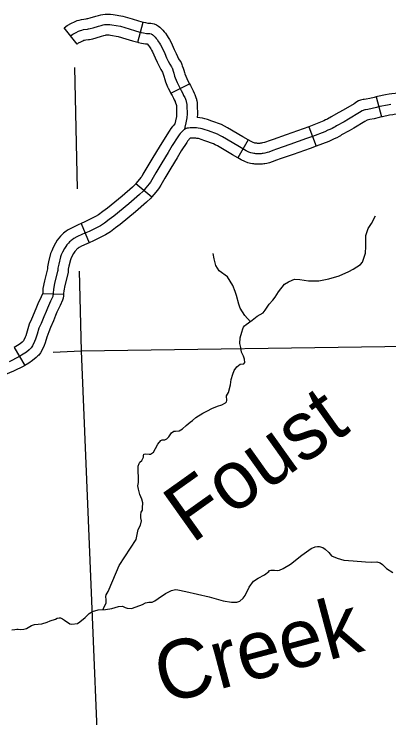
# Model space of a CAD drawing. Extents: x 1720274 to 1751788, y 372074 to 391887.
# Drawn here: x 1730745 to 1731172, y 380014 to 380815 of the extents above; entities that cross this region are included whole.
import ezdxf

# ---------------------------------------------------------------- set-up
doc = ezdxf.new("R2010")
doc.units = 0
for name, color, linetype in [('Level 32', 7, 'Continuous'), ('Level 35', 7, 'Continuous'), ('Level 4', 7, 'Continuous'), ('Level 5', 7, 'Continuous')]:
    doc.layers.add(name, color=color, linetype=linetype)

msp = doc.modelspace()

# ---------------------------------------------------------------- linework, layer by layer
at = {"layer": 'Level 32'}
for p, q in [((1730816.83, 380780.75), (1730801.96, 380799.21)), ((1730886.02, 380782.82), (1730892.18, 380805.71)), ((1730923.5, 380724.96), (1730944.67, 380735.61)), ((1731157.39, 380720.74), (1731163.41, 380697.82)), ((1731080.69, 380686.79), (1731088.89, 380664.55)), ((1731011.72, 380671.78), (1730999.96, 380651.21)), ((1730883.83, 380622.2), (1730902, 380606.98)), ((1730821.3, 380576.56), (1730830.71, 380554.8)), ((1730777.77, 380497.15), (1730801.45, 380496.39)), ((1730745.08, 380435.42), (1730757.36, 380415.15))]:
    msp.add_line(p, q, dxfattribs=at)
for points in [[(1730801.96, 380799.21), (1730805.47, 380802.03), (1730810.31, 380804.58), (1730813.73, 380806.22), (1730816.85, 380807.5), (1730819.18, 380808.15), (1730821.81, 380808.86), (1730827.28, 380809.66), (1730828.18, 380809.73), (1730829.15, 380809.9), (1730831.85, 380810.68), (1730838.09, 380812.56), (1730841.25, 380813.42), (1730843.85, 380814.13), (1730846.23, 380814.59), (1730848.96, 380814.91), (1730852.47, 380814.91), (1730854.94, 380814.86), (1730857.92, 380814.55), (1730868.99, 380812.69), (1730879.53, 380809.41), (1730886.58, 380807.22), (1730892.18, 380805.71)], [(1730809.4, 380789.98), (1730812.01, 380792.08), (1730815.63, 380793.99), (1730818.55, 380795.39), (1730820.72, 380796.28), (1730822.31, 380796.72), (1730824.21, 380797.23), (1730828.54, 380797.87), (1730829.65, 380797.95), (1730831.87, 380798.35), (1730835.21, 380799.32), (1730841.35, 380801.17), (1730844.35, 380801.99), (1730846.54, 380802.58), (1730848.06, 380802.88), (1730849.65, 380803.06), (1730852.35, 380803.06), (1730854.2, 380803.02), (1730856.31, 380802.8), (1730866.24, 380801.13), (1730876.01, 380798.1), (1730883.27, 380795.83), (1730889.6, 380794.13), (1730892.53, 380793.5), (1730896.01, 380792.91), (1730899.68, 380792.68), (1730901.08, 380792.46), (1730901.56, 380792.24), (1730902.6, 380791.54), (1730903.23, 380791.09), (1730903.75, 380790.57), (1730905.56, 380788.68), (1730906.82, 380787.24), (1730907.82, 380785.94), (1730909.71, 380783.34), (1730910.6, 380781.97), (1730911.9, 380779.97), (1730913.38, 380777.27), (1730916.67, 380769.89), (1730918.78, 380765.11), (1730920.41, 380761.51), (1730922.25, 380758.1), (1730924.4, 380754.81), (1730924.78, 380754.21), (1730925.01, 380753.68), (1730925.28, 380752.78), (1730926.08, 380750.02), (1730926.82, 380747.66), (1730927.75, 380744.39), (1730928.6, 380742.42), (1730930.87, 380736.88), (1730931.41, 380735.61), (1730934.15, 380730.15), (1730935.38, 380727.88), (1730937.25, 380724.49), (1730938.16, 380722.46), (1730939.36, 380720.14), (1730939.76, 380719.09), (1730940.52, 380717.03), (1730940.85, 380716.15), (1730941.2, 380714.97), (1730941.38, 380714.3), (1730941.54, 380713.63), (1730941.7, 380712.75), (1730941.75, 380712.08), (1730941.82, 380710.57), (1730941.99, 380701.42), (1730941.71, 380696.79), (1730940.5, 380691.11), (1730939.65, 380686.11), (1730939.16, 380683.65)], [(1730892.18, 380805.71), (1730892.39, 380805.65), (1730894.77, 380805.14), (1730897.37, 380804.7), (1730900.96, 380804.48), (1730904.56, 380803.91), (1730907.42, 380802.59), (1730909.35, 380801.28), (1730910.9, 380800.18), (1730912.22, 380798.86), (1730914.31, 380796.68), (1730915.99, 380794.75), (1730917.31, 380793.04), (1730919.48, 380790.06), (1730920.54, 380788.42), (1730922.08, 380786.05), (1730924, 380782.54), (1730927.5, 380774.7), (1730929.6, 380769.95), (1730931.04, 380766.77), (1730932.45, 380764.15), (1730934.34, 380761.26), (1730935.27, 380759.82), (1730936.18, 380757.72), (1730936.65, 380756.12), (1730937.43, 380753.46), (1730938.18, 380751.06), (1730938.94, 380748.36), (1730939.53, 380747), (1730941.79, 380741.46), (1730942.16, 380740.62), (1730944.67, 380735.61)], [(1730816.83, 380780.75), (1730818.54, 380782.13), (1730820.95, 380783.4), (1730823.37, 380784.56), (1730824.59, 380785.06), (1730825.43, 380785.29), (1730826.61, 380785.61), (1730829.8, 380786.08), (1730831.12, 380786.17), (1730834.6, 380786.81), (1730838.56, 380787.95), (1730844.62, 380789.78), (1730847.46, 380790.55), (1730849.23, 380791.03), (1730849.88, 380791.16), (1730850.34, 380791.21), (1730852.23, 380791.21), (1730853.46, 380791.19), (1730854.71, 380791.06), (1730863.48, 380789.58), (1730872.49, 380786.78), (1730879.97, 380784.45), (1730886.02, 380782.82)], [(1730886.02, 380782.82), (1730886.81, 380782.61), (1730890.29, 380781.86), (1730894.65, 380781.12), (1730896.51, 380781), (1730896.82, 380780.68), (1730897.65, 380779.72), (1730898.34, 380778.83), (1730899.94, 380776.63), (1730900.65, 380775.53), (1730901.71, 380773.9), (1730902.75, 380772), (1730905.84, 380765.08), (1730907.97, 380760.27), (1730909.79, 380756.25), (1730912.05, 380752.04), (1730914.03, 380749), (1730914.74, 380746.59), (1730915.47, 380744.27), (1730916.56, 380740.42), (1730917.67, 380737.84), (1730919.94, 380732.29), (1730920.67, 380730.6), (1730923.5, 380724.96)], [(1730944.66, 380735.64), (1730945.79, 380733.56), (1730947.86, 380729.79), (1730948.84, 380727.62), (1730950.19, 380724.99), (1730950.86, 380723.25), (1730951.62, 380721.17), (1730952.08, 380719.95), (1730952.61, 380718.17), (1730952.88, 380717.17), (1730953.14, 380716.04), (1730953.46, 380714.27), (1730953.58, 380712.82), (1730953.66, 380710.95), (1730953.84, 380701.17), (1730953.61, 380697.26)], [(1730923.5, 380724.96), (1730923.65, 380724.66), (1730924.98, 380722.21), (1730926.64, 380719.19), (1730927.49, 380717.31), (1730928.52, 380715.3), (1730928.67, 380714.92), (1730929.42, 380712.88), (1730929.62, 380712.35), (1730929.79, 380711.77), (1730929.88, 380711.43), (1730929.92, 380711.25), (1730929.97, 380710.18), (1730930.13, 380701.67), (1730929.93, 380698.39), (1730928.86, 380693.33), (1730928.29, 380689.99)], [(1731157.39, 380720.74), (1731155, 380720.11), (1731150.3, 380719.01), (1731145.91, 380718.18), (1731143.67, 380717.81), (1731142.39, 380717.69), (1731139.59, 380717.02), (1731137.18, 380716.05), (1731135.44, 380715.02), (1731132.14, 380712.98), (1731119.95, 380705.62), (1731114.92, 380702.8), (1731106.28, 380697.95), (1731104.72, 380697.04), (1731103.52, 380696.35), (1731101.89, 380695.48), (1731099.7, 380694.47), (1731097.68, 380693.59), (1731094.14, 380691.99), (1731080.73, 380686.8), (1731080.7, 380686.79)], [(1731243.77, 380709.03), (1731243.46, 380709.1), (1731240.54, 380709.83), (1731222.42, 380714.76), (1731213.07, 380717.35), (1731199.72, 380721.46), (1731197.49, 380722.3), (1731195.35, 380723.11), (1731193.04, 380723.74), (1731191.33, 380724.06), (1731188.84, 380724.44), (1731186.64, 380724.67), (1731183.7, 380724.78), (1731179.16, 380724.59), (1731175.01, 380724.22), (1731172.15, 380723.79), (1731167.98, 380722.99), (1731159.01, 380721.16), (1731157.39, 380720.74)], [(1731174.15, 380712.1), (1731170.27, 380711.37), (1731161.7, 380709.62), (1731157.86, 380708.61), (1731152.74, 380707.41), (1731147.98, 380706.52), (1731145.18, 380706.05), (1731144.33, 380705.97), (1731143.21, 380705.7), (1731142.43, 380705.39), (1731141.58, 380704.89), (1731138.32, 380702.87), (1731125.91, 380695.38), (1731120.72, 380692.47), (1731112.15, 380687.65), (1731110.68, 380686.8), (1731109.28, 380685.99), (1731107.15, 380684.86), (1731104.55, 380683.66), (1731102.49, 380682.76), (1731098.73, 380681.06), (1731084.91, 380675.71), (1731078.15, 380673.22), (1731058.89, 380666.38), (1731044.05, 380661.21), (1731039.63, 380659.61), (1731035.23, 380657.89), (1731033.11, 380657.28), (1731030.46, 380656.67), (1731028.55, 380656.33), (1731027.49, 380656.17), (1731026.27, 380655.96), (1731024.97, 380655.85), (1731024.26, 380655.85), (1731023.22, 380655.88), (1731022.3, 380655.93), (1731021.4, 380655.98), (1731020.39, 380656.06), (1731019.25, 380656.19), (1731018.06, 380656.33), (1731016.68, 380656.57), (1731014.83, 380657.05), (1731012.49, 380657.95), (1731009.31, 380659.51), (1730999.66, 380665.03), (1730982.45, 380675.29), (1730979.39, 380676.91), (1730976.63, 380678.17), (1730966.26, 380682.01), (1730961.65, 380683.63), (1730959.25, 380684.29), (1730957.33, 380684.77), (1730954.87, 380685.19), (1730952.71, 380685.43), (1730947.92, 380685.55), (1730945.4, 380685.43), (1730943.6, 380685.25), (1730942.22, 380685.07), (1730940.9, 380684.71), (1730940.51, 380684.59), (1730940.34, 380684.51), (1730940.18, 380684.41), (1730939.52, 380683.93), (1730939.16, 380683.65)], [(1731011.72, 380671.78), (1731005.63, 380675.26), (1730988.26, 380685.62), (1730984.63, 380687.54), (1730981.16, 380689.13), (1730970.28, 380693.16), (1730965.19, 380694.95), (1730962.26, 380695.75), (1730959.77, 380696.38), (1730956.53, 380696.93), (1730953.61, 380697.26)], [(1731163.41, 380697.82), (1731160.73, 380697.11), (1731155.19, 380695.81), (1731150.04, 380694.85), (1731147.08, 380694.35), (1731144.5, 380692.76), (1731131.87, 380685.13), (1731126.51, 380682.13), (1731118.02, 380677.36), (1731116.63, 380676.56), (1731115.03, 380675.62), (1731112.41, 380674.24), (1731109.4, 380672.84), (1731107.3, 380671.93), (1731103.32, 380670.13), (1731089.09, 380664.63), (1731088.88, 380664.55)], [(1731238.88, 380685.84), (1731238.14, 380686), (1731234.55, 380686.9), (1731216.15, 380691.9), (1731206.42, 380694.6), (1731192.08, 380699.02), (1731189.12, 380700.12), (1731187.99, 380700.55), (1731187.75, 380700.62), (1731187.36, 380700.69), (1731185.82, 380700.93), (1731184.99, 380701.01), (1731183.75, 380701.06), (1731180.69, 380700.93), (1731177.86, 380700.68), (1731176.15, 380700.42), (1731172.56, 380699.74), (1731164.39, 380698.07), (1731163.41, 380697.82)], [(1730928.29, 380689.99), (1730926.33, 380687.95), (1730925.25, 380686.58), (1730923.58, 380684.67), (1730921.69, 380681.69), (1730915.15, 380671.65), (1730910.42, 380663.44), (1730903.18, 380651.84), (1730896.41, 380640.27), (1730891.86, 380632.65), (1730890.37, 380630.23), (1730889.53, 380629.04), (1730886.05, 380624.85), (1730883.83, 380622.2)], [(1731080.69, 380686.79), (1731074.12, 380684.36), (1731054.96, 380677.56), (1731040.1, 380672.38), (1731035.46, 380670.71), (1731031.42, 380669.13), (1731030.14, 380668.76), (1731028.07, 380668.28), (1731026.62, 380668.02), (1731025.59, 380667.87), (1731024.77, 380667.72), (1731024.49, 380667.7), (1731024.41, 380667.7), (1731023.71, 380667.72), (1731022.98, 380667.76), (1731022.21, 380667.8), (1731021.54, 380667.86), (1731020.6, 380667.97), (1731019.74, 380668.06), (1731019.19, 380668.16), (1731018.45, 380668.35), (1731017.24, 380668.82), (1731014.87, 380669.98), (1731011.72, 380671.78)], [(1730939.16, 380683.65), (1730938.44, 380683.09), (1730936.95, 380681.89), (1730935.27, 380680.15), (1730934.37, 380679.01), (1730933.11, 380677.57), (1730931.67, 380675.29), (1730925.25, 380665.45), (1730920.58, 380657.35), (1730913.32, 380645.71), (1730906.61, 380634.24), (1730901.99, 380626.5), (1730900.25, 380623.68), (1730898.93, 380621.82), (1730895.16, 380617.26), (1730892.04, 380613.54), (1730887.9, 380609.46), (1730875.73, 380598.84), (1730858.59, 380584.86), (1730853.37, 380581.02), (1730848.03, 380576.88), (1730843.54, 380574.12), (1730830.53, 380567.64), (1730823.03, 380564.4), (1730816.5, 380561.34), (1730813.02, 380559.41), (1730811.28, 380558.21), (1730810.2, 380557.43), (1730809.24, 380556.59), (1730808.23, 380555.69), (1730806.91, 380554.37), (1730805.23, 380552.33), (1730803.85, 380550.65), (1730802.41, 380548.31), (1730800.13, 380544.17)], [(1730945.52, 380673.57), (1730944.95, 380673.12), (1730944.21, 380672.35), (1730943.49, 380671.44), (1730942.64, 380670.47), (1730941.64, 380668.89), (1730935.36, 380659.25), (1730930.74, 380651.25), (1730923.47, 380639.58), (1730916.81, 380628.21), (1730912.13, 380620.36), (1730910.14, 380617.14), (1730908.34, 380614.61), (1730904.26, 380609.68), (1730902, 380606.98)], [(1730999.96, 380651.21), (1730993.68, 380654.8), (1730976.64, 380664.96), (1730974.15, 380666.28), (1730972.11, 380667.21), (1730962.24, 380670.86), (1730958.11, 380672.31), (1730956.24, 380672.83), (1730954.89, 380673.17), (1730953.22, 380673.45), (1730951.91, 380673.6), (1730948.05, 380673.69), (1730945.52, 380673.57)], [(1731088.89, 380664.55), (1731082.19, 380662.08), (1731062.82, 380655.2), (1731048.01, 380650.04), (1731043.79, 380648.52), (1731039.04, 380646.66), (1731036.08, 380645.8), (1731032.84, 380645.06), (1731030.48, 380644.63), (1731029.39, 380644.47), (1731027.77, 380644.19), (1731025.46, 380644), (1731024.1, 380644), (1731022.73, 380644.03), (1731021.61, 380644.1), (1731020.58, 380644.16), (1731019.24, 380644.27), (1731017.9, 380644.42), (1731016.38, 380644.59), (1731014.18, 380644.97), (1731011.2, 380645.74), (1731007.74, 380647.08), (1731003.75, 380649.04), (1730999.96, 380651.21)], [(1730883.83, 380622.2), (1730883.32, 380621.58), (1730879.84, 380618.15), (1730868.09, 380607.9), (1730851.32, 380594.23), (1730846.22, 380590.47), (1730841.28, 380586.64), (1730837.79, 380584.49), (1730825.53, 380578.39), (1730821.3, 380576.56)], [(1730902, 380606.98), (1730900.76, 380605.5), (1730895.97, 380600.77), (1730883.38, 380589.78), (1730865.85, 380575.49), (1730860.52, 380571.56), (1730854.79, 380567.12), (1730849.29, 380563.74), (1730835.53, 380556.89), (1730830.71, 380554.8)], [(1730821.3, 380576.56), (1730818.17, 380575.2), (1730811.12, 380571.9), (1730806.78, 380569.5), (1730804.44, 380567.89), (1730802.81, 380566.71), (1730801.42, 380565.49), (1730800.1, 380564.33), (1730798.12, 380562.35), (1730796.07, 380559.86), (1730794.18, 380557.55), (1730792.17, 380554.28), (1730789.45, 380549.34), (1730787.93, 380545.71), (1730786.61, 380542.5), (1730784.28, 380532.9), (1730783.23, 380527.17), (1730783.15, 380525.16), (1730783.11, 380524.98), (1730779.62, 380511.38), (1730778.02, 380502.76), (1730777.8, 380498.14), (1730777.77, 380497.15)], [(1730830.71, 380554.8), (1730827.9, 380553.59), (1730821.88, 380550.77), (1730819.27, 380549.33), (1730818.12, 380548.54), (1730817.59, 380548.16), (1730817.07, 380547.7), (1730816.35, 380547.06), (1730815.69, 380546.4), (1730814.38, 380544.81), (1730813.52, 380543.76), (1730812.65, 380542.35), (1730810.82, 380539.01), (1730809.82, 380536.63), (1730809.22, 380535.17), (1730807.47, 380527.96), (1730806.85, 380524.57), (1730806.8, 380523.38), (1730806.55, 380521.15), (1730806.12, 380519.32), (1730802.78, 380506.27), (1730801.62, 380500.02), (1730801.48, 380497.19), (1730801.45, 380496.39)], [(1730800.13, 380544.17), (1730798.87, 380541.17), (1730797.91, 380538.83), (1730795.87, 380530.43), (1730795.04, 380525.87), (1730794.98, 380524.25), (1730794.86, 380523.17), (1730794.62, 380522.15), (1730791.2, 380508.83), (1730789.82, 380501.39), (1730789.64, 380497.67), (1730789.58, 380495.81), (1730789.34, 380494.61), (1730789.04, 380493.71), (1730786.7, 380488.31), (1730783.1, 380480.5), (1730781.49, 380476.72), (1730778.85, 380470.6), (1730775.85, 380463.04), (1730773.39, 380457.76), (1730771.23, 380450.74), (1730769.5, 380445.04), (1730768.48, 380442.52), (1730766.14, 380437.36), (1730765.48, 380436.16), (1730764.7, 380435.26), (1730763.98, 380434.6), (1730762.42, 380433.04), (1730759.12, 380430.34), (1730755.41, 380427.82), (1730750.55, 380424.88), (1730739.58, 380419.36)], [(1730777.78, 380497.52), (1730775.88, 380493.14), (1730772.28, 380485.32), (1730770.6, 380481.4), (1730767.9, 380475.13), (1730764.96, 380467.73), (1730762.31, 380462.02), (1730759.9, 380454.21), (1730758.31, 380449), (1730757.58, 380447.19), (1730755.74, 380443.11), (1730754.46, 380441.83), (1730752.03, 380439.85), (1730749.01, 380437.8), (1730745.08, 380435.42)], [(1730801.45, 380496.39), (1730801.39, 380494.45), (1730800.82, 380491.56), (1730800.12, 380489.47), (1730797.52, 380483.47), (1730793.93, 380475.69), (1730792.37, 380472.05), (1730789.8, 380466.07), (1730786.74, 380458.35), (1730784.48, 380453.5), (1730782.56, 380447.27), (1730780.68, 380441.08), (1730779.37, 380437.85), (1730776.74, 380432.05), (1730775.26, 380429.35), (1730773.21, 380426.99), (1730772.18, 380426.04), (1730770.39, 380424.24), (1730766.22, 380420.83), (1730761.8, 380417.84), (1730757.36, 380415.15)], [(1730757.36, 380415.15), (1730756.29, 380414.5), (1730744.54, 380408.59), (1730732.6, 380403.57), (1730728.69, 380401.93), (1730726.86, 380401.24), (1730724.37, 380400.24), (1730721.61, 380399.57), (1730719.6, 380399.16), (1730717.55, 380398.76), (1730715.07, 380398.33), (1730712.43, 380398.16), (1730710.57, 380398.09), (1730705.96, 380398.02), (1730694, 380398.4), (1730686.46, 380398.87), (1730679.57, 380398.93), (1730676.09, 380399.14), (1730675.51, 380399.1), (1730675.04, 380399.04), (1730674.31, 380398.86), (1730674.51, 380398.93)]]:
    msp.add_lwpolyline(points, dxfattribs=at)
at = {"layer": 'Level 35'}
for points in [[(1731028.71, 380475.16), (1731031.02, 380477.99), (1731035.39, 380484.84), (1731039.56, 380489.32), (1731042.25, 380492.91), (1731046.13, 380498.88), (1731053, 380507.71), (1731057.63, 380510.41), (1731061.64, 380512.32), (1731064.32, 380513.21), (1731070.59, 380512.92), (1731080.14, 380511.42), (1731085.51, 380511.42), (1731092.07, 380511.42), (1731103.41, 380513.81), (1731115.34, 380517.1), (1731126.38, 380522.17), (1731131.15, 380524.56), (1731139.5, 380529.94), (1731141.89, 380532.63), (1731145.17, 380542.78), (1731145.47, 380550.55), (1731145.47, 380555.62), (1731145.47, 380563.09), (1731148.16, 380570.86), (1731152.03, 380576.83), (1731156.51, 380585.19)], [(1731014.35, 380464.95), (1731007.64, 380472), (1731002.57, 380480.36), (1731001.05, 380484.79), (1730998.39, 380494.7), (1730996.94, 380499.26), (1730994.26, 380506.05), (1730988.01, 380515.89), (1730978.7, 380522.77), (1730974.97, 380528.75), (1730973.01, 380536.62), (1730971.58, 380542.7)], [(1730846.42, 380137.67), (1730847.08, 380138.67), (1730849.81, 380145.25), (1730849.81, 380148.47), (1730849.49, 380152.16), (1730849.81, 380154.25), (1730852.06, 380157.94), (1730857.7, 380170.39), (1730864.91, 380187.39), (1730883.98, 380217.21), (1730886.55, 380228.46), (1730888.96, 380233.28), (1730890.24, 380238.26), (1730889.44, 380241.95), (1730889.28, 380245.32), (1730889.76, 380248.21), (1730891.2, 380250.46), (1730891.35, 380253.3), (1730891.51, 380258.91), (1730890.55, 380262.92), (1730888.14, 380268.53), (1730886.7, 380274.3), (1730885.9, 380278.15), (1730886.7, 380282), (1730886.87, 380287.25), (1730886.23, 380295.44), (1730886.23, 380298.17), (1730886.39, 380300.58), (1730887.51, 380303.47), (1730888.16, 380305.07), (1730890.56, 380307), (1730891.69, 380309.25), (1730892.33, 380310.86), (1730892.33, 380312.78), (1730892.97, 380314.07), (1730893.29, 380314.23), (1730895.22, 380314.71), (1730898.75, 380314.23), (1730900.35, 380314.39), (1730903.72, 380316.32), (1730905.97, 380320.66), (1730908.85, 380325.63), (1730912.06, 380329.65), (1730913.67, 380330.45), (1730916.88, 380330.61), (1730919.12, 380331.74), (1730921.37, 380333.99), (1730924.36, 380338.45), (1730926.92, 380340.53), (1730928.75, 380340.57), (1730933.17, 380340.69), (1730937.01, 380342.94), (1730941.18, 380346.79), (1730945.51, 380350.8), (1730948.39, 380352.56), (1730952.07, 380355.77), (1730959.93, 380361.06), (1730965.17, 380363.38), (1730970.18, 380366.19), (1730976.59, 380368.92), (1730981.72, 380370.36), (1730985.88, 380372.6), (1730986.77, 380373.79), (1730987.34, 380375.17), (1730987.11, 380380.77), (1730989.13, 380384.29), (1730991.32, 380393.06), (1730992.13, 380399.3), (1730994.09, 380405.41), (1730995.82, 380409.57), (1730998.82, 380413.72), (1731002.39, 380416.49), (1731006.55, 380417.07), (1731007.93, 380418.69), (1731007.58, 380422.15), (1731006.32, 380425.84), (1731004.01, 380430.23), (1731003.2, 380435.42), (1731002.22, 380439.98), (1731002.62, 380446.74), (1731004.47, 380452.85), (1731005.6, 380456.89), (1731006.39, 380458.88), (1731007.38, 380460.07), (1731009.37, 380461.66), (1731016.33, 380466.64), (1731021.69, 380471.21), (1731028.71, 380475.16)], [(1730742.69, 380114.22), (1730745.9, 380114.89), (1730748.31, 380115.16), (1730749.92, 380115.03), (1730752.6, 380114.89), (1730756.21, 380115.03), (1730759.16, 380115.97), (1730765.05, 380119.45), (1730768.53, 380120.39), (1730776.57, 380121.33), (1730782.6, 380122.94), (1730786.35, 380124.54), (1730792.24, 380126.69), (1730793.98, 380127.49), (1730796.26, 380128.03), (1730798, 380128.16), (1730800.27, 380126.96), (1730802.68, 380125.35), (1730808.44, 380121.06), (1730810.99, 380120.79), (1730817.15, 380121.73), (1730820.1, 380123.61), (1730826.12, 380128.43), (1730830.41, 380132.86), (1730834.56, 380135.13), (1730840.72, 380137.14), (1730849.02, 380137.55), (1730856.26, 380138.75), (1730863.89, 380140.9), (1730868.44, 380141.17), (1730871.66, 380139.69), (1730874.01, 380138.98), (1730878.82, 380138.69), (1730883.93, 380140.44), (1730891.23, 380143.36), (1730894.73, 380144.97), (1730898.38, 380145.84), (1730902.17, 380145.99), (1730905.38, 380147.3), (1730909.32, 380149.93), (1730917.35, 380155.63), (1730924.35, 380159.13), (1730928.88, 380160.16), (1730931.65, 380159.87), (1730940.7, 380158.11), (1730967.26, 380151.98), (1730983.16, 380147.3), (1730992.65, 380145.99), (1730998.63, 380145.99), (1731001.99, 380147.01), (1731006.08, 380150.52), (1731008.12, 380153.29), (1731012.93, 380163.08), (1731017.6, 380169.65), (1731023, 380173.01), (1731030.3, 380177.1), (1731034.97, 380180.9), (1731035.99, 380181.77), (1731037.45, 380182.36), (1731039.35, 380182.36), (1731041.54, 380182.36), (1731044.75, 380181.92), (1731047.23, 380182.21), (1731051.61, 380184.11), (1731059.92, 380189.08), (1731072.77, 380199.15), (1731083.27, 380206.89), (1731087.94, 380208.94), (1731090.42, 380209.09), (1731092.47, 380209.09)], [(1731092.47, 380209.09), (1731096.7, 380207.92), (1731099.33, 380206.16), (1731103.27, 380202.37), (1731106.48, 380198.72), (1731113.04, 380195.79), (1731120.49, 380193.6), (1731131.14, 380192.73), (1731145.15, 380191.7), (1731152.15, 380191.41), (1731158.28, 380191.56), (1731161.78, 380190.68), (1731164.41, 380188.78), (1731169.23, 380184.26), (1731176.38, 380179.73)]]:
    msp.add_lwpolyline(points, dxfattribs=at)
at = {"layer": 'Level 4'}
for points in [[(1730813.77, 380753.97), (1730817.06, 380616.2)], [(1730819.3, 380522.4), (1730821.47, 380431.62), (1730853, 379670.47)]]:
    msp.add_lwpolyline(points, dxfattribs=at)
at = {"layer": 'Level 5'}
for points in [[(1730789.46, 380430.17), (1730821.47, 380431.62)], [(1730821.47, 380431.62), (1731193.88, 380436.92), (1731622.97, 380419.26)]]:
    msp.add_lwpolyline(points, dxfattribs=at)

# ---------------------------------------------------------------- texts
at = {"layer": 'Level 35'}
for s, rotation, p in [('Foust', 35.43919, (1730947.61, 380211.73)), ('Creek', 14.88335, (1730915.52, 380029.71))]:
    msp.add_text(s, height=66.739, rotation=rotation, dxfattribs=at).set_placement(p)

doc.saveas('drawing.dxf')
